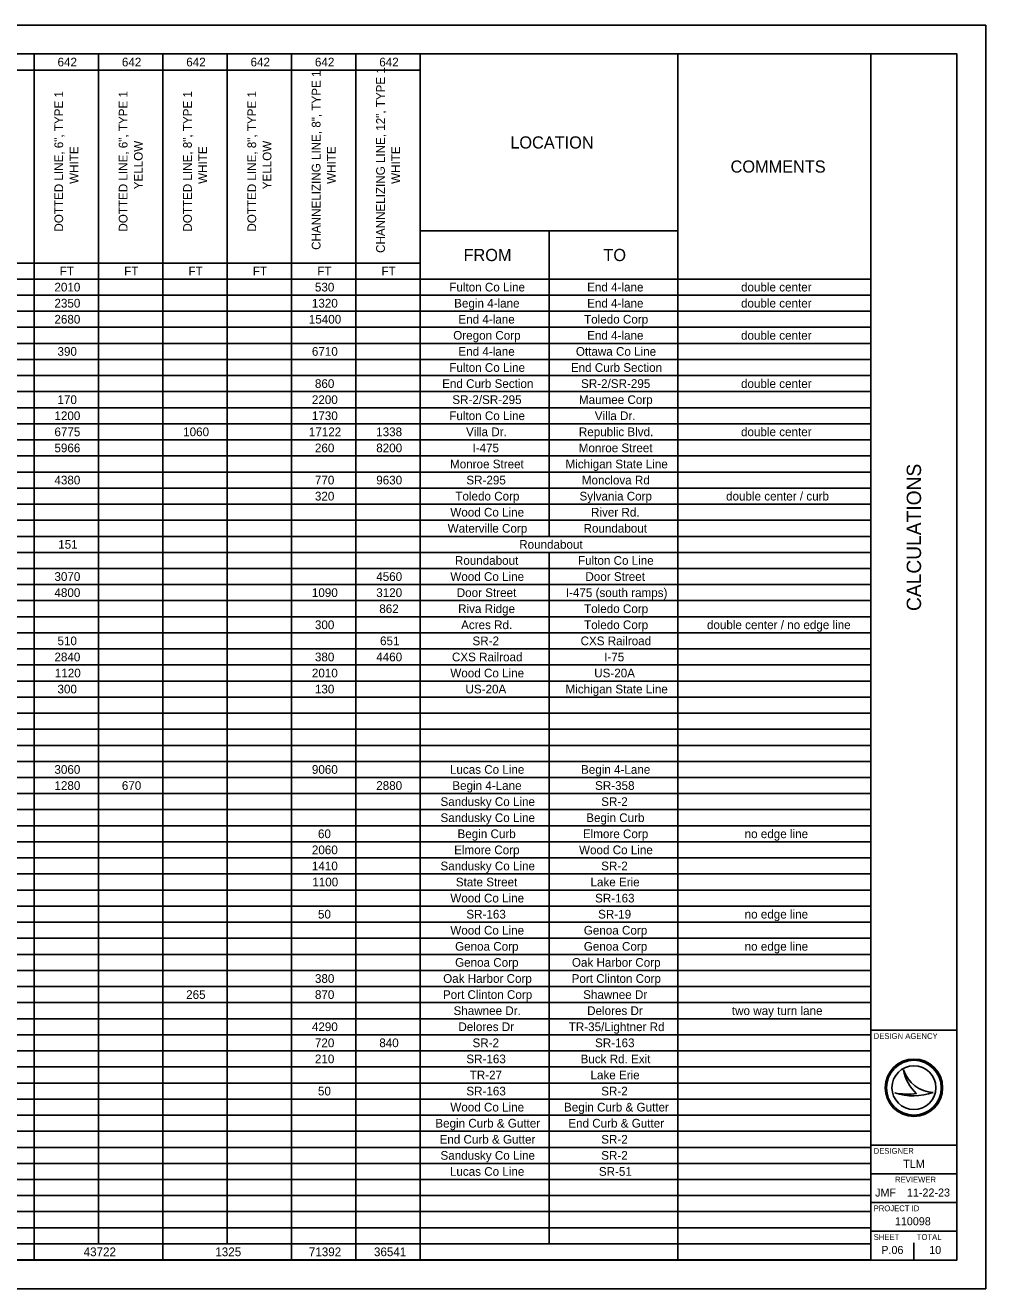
# Model space of a CAD drawing. Extents: x 0 to 34, y 0 to 22.
# Drawn here: x 17.29 to 34, y 0 to 22 of the extents above; entities that cross this region are included whole.
import ezdxf

# ---------------------------------------------------------------- set-up
doc = ezdxf.new("R2010")
doc.units = 0
for name, color, linetype in [('Default', 7, 'Continuous'), ('SH_Border', 7, 'Continuous'), ('SH_Cut_Line', 7, 'Continuous'), ('SH_Data', 7, 'Continuous')]:
    doc.layers.add(name, color=color, linetype=linetype)

msp = doc.modelspace()

# ---------------------------------------------------------------- linework, layer by layer
at = {"layer": 'Default'}
for p, q in [((1.5, 21.5), (32, 21.5)), ((17.442, 21.5), (17.442, 0.502)), ((18.562, 21.5), (18.562, 0.782)), ((19.681, 21.5), (19.681, 0.502)), ((20.801, 21.5), (20.801, 0.782)), ((21.921, 21.5), (21.921, 0.502)), ((23.041, 21.5), (23.041, 0.502)), ((24.161, 21.5), (24.161, 0.502)), ((28.64, 21.5), (28.64, 0.502)), ((32, 21.5), (32, 0.502)), ((8.483, 21.22), (24.161, 21.22)), ((24.161, 18.42), (28.64, 18.42)), ((26.401, 18.42), (26.401, 13.101)), ((8.483, 17.86), (24.161, 17.86)), ((1.5, 17.58), (32, 17.58)), ((2.505, 17.3), (32, 17.3)), ((2.505, 17.021), (32, 17.021)), ((2.505, 16.741), (32, 16.741)), ((2.505, 16.461), (32, 16.461)), ((2.505, 16.181), (32, 16.181)), ((2.505, 15.901), (32, 15.901)), ((2.505, 15.621), (32, 15.621)), ((2.505, 15.341), (32, 15.341)), ((2.505, 15.061), (32, 15.061)), ((2.505, 14.781), (32, 14.781)), ((2.505, 14.501), (32, 14.501)), ((2.505, 14.221), (32, 14.221)), ((2.505, 13.941), (32, 13.941)), ((2.505, 13.661), (32, 13.661)), ((2.505, 13.381), (32, 13.381)), ((2.505, 13.101), (32, 13.101)), ((2.505, 12.821), (32, 12.821)), ((26.401, 12.821), (26.401, 0.782)), ((2.505, 12.541), (32, 12.541)), ((2.505, 12.261), (32, 12.261)), ((2.505, 11.981), (32, 11.981)), ((2.505, 11.701), (32, 11.701)), ((2.505, 11.421), (32, 11.421)), ((2.505, 11.141), (32, 11.141)), ((2.505, 10.861), (32, 10.861)), ((2.505, 10.581), (32, 10.581)), ((1.5, 10.301), (32, 10.301)), ((1.5, 10.021), (32, 10.021)), ((1.5, 9.741), (32, 9.741)), ((1.5, 9.461), (32, 9.461)), ((1.5, 9.181), (32, 9.181)), ((2.505, 8.901), (32, 8.901)), ((2.505, 8.621), (32, 8.621)), ((2.505, 8.342), (32, 8.342)), ((2.505, 8.062), (32, 8.062)), ((2.505, 7.782), (32, 7.782)), ((2.505, 7.502), (32, 7.502)), ((2.505, 7.222), (32, 7.222)), ((2.505, 6.942), (32, 6.942)), ((2.505, 6.662), (32, 6.662)), ((2.505, 6.382), (32, 6.382)), ((2.505, 6.102), (32, 6.102)), ((2.505, 5.822), (32, 5.822)), ((2.505, 5.542), (32, 5.542)), ((2.505, 5.262), (32, 5.262)), ((2.505, 4.982), (32, 4.982)), ((2.505, 4.702), (32, 4.702)), ((2.505, 4.422), (32, 4.422)), ((2.505, 4.142), (32, 4.142)), ((2.505, 3.862), (32, 3.862)), ((2.505, 3.582), (32, 3.582)), ((2.505, 3.302), (32, 3.302)), ((2.505, 3.022), (32, 3.022)), ((2.505, 2.742), (32, 2.742)), ((2.505, 2.462), (32, 2.462)), ((2.505, 2.182), (32, 2.182)), ((1.5, 1.902), (32, 1.902)), ((1.5, 1.622), (32, 1.622)), ((1.5, 1.342), (32, 1.342)), ((1.5, 1.062), (32, 1.062)), ((1.5, 0.782), (32, 0.782)), ((1.5, 0.502), (32, 0.502))]:
    msp.add_line(p, q, dxfattribs=at)
at = {"layer": 'SH_Border'}
for p, q in [((32, 0.5), (32, 21.5)), ((32, 4.5), (33.5, 4.5)), ((32, 2.5), (33.5, 2.5)), ((32, 2), (33.5, 2)), ((32, 1.5), (33.5, 1.5)), ((32, 1), (33.5, 1))]:
    msp.add_line(p, q, dxfattribs=at)
msp.add_lwpolyline([(1.5, 21.5), (33.5, 21.5), (33.5, 0.5), (1.5, 0.5)], close=True, dxfattribs=at)
at = {"layer": 'SH_Cut_Line'}
msp.add_lwpolyline([(0, 0), (34, 0), (34, 22), (0, 22)], close=True, dxfattribs=at)
at = {"layer": 'SH_Data'}
for p, q in [((32.567, 3.81), (32.567, 3.81)), ((32.417, 3.41), (32.417, 3.41)), ((32.75, 3.5), (32.75, 3.5)), ((33.087, 3.419), (33.087, 3.419)), ((32.375, 0.675), (32.375, 0.675)), ((32.75, 0.5), (32.75, 0.8))]:
    msp.add_line(p, q, dxfattribs=at)
for radius in [0.5, 0.477, 0.477, 0.382]:
    msp.add_circle((32.75, 3.5), radius, dxfattribs=at)
for centre, radius, start, end in [((33.116, 3.998), 0.58, 198.9257, 198.9319), ((33.347, 3.97), 0.796, 191.6379, 191.6421), ((33.116, 3.998), 0.58, 198.9319, 267.1657), ((33.347, 3.97), 0.796, 191.6421, 226.0947), ((32.739, 4.37), 1.013, 251.4576, 290.0832), ((32.648, 4.654), 1.266, 259.4964, 259.4995), ((32.739, 4.37), 1.013, 251.4527, 251.4576), ((32.648, 4.654), 1.266, 259.4995, 276.6672)]:
    msp.add_arc(centre, radius, start, end, dxfattribs=at)

# ---------------------------------------------------------------- texts
at = {"layer": 'Default'}
for s, height, p in [('642', 0.1515, (17.848, 21.284)), ('642', 0.1515, (18.968, 21.284)), ('642', 0.1515, (20.088, 21.284)), ('642', 0.1515, (21.207, 21.284)), ('642', 0.1515, (22.327, 21.284)), ('642', 0.1515, (23.447, 21.284)), ('LOCATION', 0.2121, (25.727, 19.854)), ('COMMENTS', 0.2121, (29.56, 19.434)), ('FROM', 0.2121, (24.913, 17.894)), ('TO', 0.2121, (27.347, 17.894)), ('FT', 0.1515, (17.887, 17.645)), ('FT', 0.1515, (19.007, 17.645)), ('FT', 0.1515, (20.127, 17.645)), ('FT', 0.1515, (21.247, 17.645)), ('FT', 0.1515, (22.367, 17.645)), ('FT', 0.1515, (23.486, 17.645)), ('2010', 0.1515, (17.794, 17.365)), ('530', 0.1515, (22.327, 17.365)), ('Fulton Co Line', 0.15151, (24.665, 17.365)), ('End 4-lane', 0.1515, (27.064, 17.365)), ('double center', 0.15151, (29.742, 17.365)), ('2350', 0.1515, (17.794, 17.085)), ('1320', 0.1515, (22.274, 17.085)), ('Begin 4-lane', 0.15151, (24.75, 17.085)), ('End 4-lane', 0.1515, (27.064, 17.085)), ('double center', 0.15151, (29.742, 17.085)), ('2680', 0.1515, (17.794, 16.805)), ('15400', 0.1515, (22.221, 16.805)), ('End 4-lane', 0.1515, (24.824, 16.805)), ('Toledo Corp', 0.15151, (27.011, 16.805)), ('Oregon Corp', 0.15151, (24.734, 16.525)), ('End 4-lane', 0.1515, (27.064, 16.525)), ('double center', 0.15151, (29.742, 16.525)), ('390', 0.1515, (17.847, 16.245)), ('6710', 0.1515, (22.274, 16.245)), ('End 4-lane', 0.1515, (24.824, 16.245)), ('Ottawa Co Line', 0.15151, (26.868, 16.245)), ('Fulton Co Line', 0.15151, (24.665, 15.965)), ('End Curb Section', 0.15151, (26.781, 15.965)), ('End Curb Section', 0.15151, (24.541, 15.685)), ('SR-2/SR-295', 0.15151, (26.958, 15.685)), ('double center', 0.15151, (29.742, 15.685)), ('860', 0.1515, (22.327, 15.685)), ('170', 0.1515, (17.847, 15.405)), ('2200', 0.1515, (22.274, 15.405)), ('SR-2/SR-295', 0.15151, (24.718, 15.405)), ('Maumee Corp', 0.15151, (26.921, 15.405)), ('1200', 0.1515, (17.794, 15.125)), ('1730', 0.1515, (22.274, 15.125)), ('Fulton Co Line', 0.15151, (24.665, 15.125)), ('Villa Dr.', 0.1515, (27.197, 15.125)), ('6775', 0.1515, (17.794, 14.845)), ('1060', 0.1515, (20.034, 14.845)), ('17122', 0.1515, (22.221, 14.845)), ('1338', 0.1515, (23.393, 14.845)), ('Villa Dr.', 0.1515, (24.957, 14.845)), ('Republic Blvd.', 0.15151, (26.92, 14.845)), ('double center', 0.15151, (29.742, 14.845)), ('5966', 0.1515, (17.794, 14.565)), ('260', 0.1515, (22.327, 14.565)), ('8200', 0.1515, (23.394, 14.565)), ('I-475', 0.1515, (25.068, 14.565)), ('Monroe Street', 0.15151, (26.918, 14.565)), ('Monroe Street', 0.15151, (24.678, 14.285)), ('Michigan State Line', 0.15151, (26.688, 14.285)), ('4380', 0.1515, (17.794, 14.005)), ('770', 0.1515, (22.327, 14.005)), ('9630', 0.1515, (23.394, 14.005)), ('SR-295', 0.1515, (24.962, 14.005)), ('Monclova Rd', 0.15151, (26.972, 14.005)), ('320', 0.1515, (22.327, 13.725)), ('Toledo Corp', 0.15151, (24.771, 13.725)), ('Sylvania Corp', 0.15151, (26.931, 13.725)), ('double center / curb', 0.15151, (29.482, 13.725)), ('Wood Co Line', 0.15151, (24.683, 13.445)), ('River Rd.', 0.1515, (27.132, 13.445)), ('Waterville Corp', 0.15151, (24.637, 13.165)), ('Roundabout', 0.1515, (27.002, 13.165)), ('151', 0.1515, (17.86, 12.885)), ('Roundabout', 0.1515, (25.882, 12.885)), ('Roundabout', 0.1515, (24.763, 12.605)), ('Fulton Co Line', 0.15151, (26.905, 12.605)), ('3070', 0.1515, (17.794, 12.325)), ('4560', 0.1515, (23.394, 12.325)), ('Wood Co Line', 0.15151, (24.683, 12.325)), ('Door Street', 0.15151, (27.034, 12.325)), ('4800', 0.1515, (17.794, 12.045)), ('1090', 0.1515, (22.274, 12.045)), ('3120', 0.1515, (23.394, 12.045)), ('Door Street', 0.15151, (24.795, 12.045)), ('I-475 (south ramps)', 0.15151, (26.693, 12.045)), ('862', 0.1515, (23.447, 11.765)), ('Riva Ridge', 0.1515, (24.819, 11.765)), ('Toledo Corp', 0.15151, (27.011, 11.765)), ('300', 0.1515, (22.327, 11.485)), ('Acres Rd.', 0.1515, (24.871, 11.485)), ('Toledo Corp', 0.15151, (27.011, 11.485)), ('double center / no edge line', 0.15151, (29.149, 11.485)), ('510', 0.1515, (17.847, 11.205)), ('651', 0.1515, (23.46, 11.205)), ('SR-2', 0.1515, (25.069, 11.205)), ('CXS Railroad', 0.15151, (26.95, 11.205)), ('2840', 0.1515, (17.794, 10.925)), ('380', 0.1515, (22.327, 10.925)), ('4460', 0.1515, (23.394, 10.925)), ('CXS Railroad', 0.15151, (24.711, 10.925)), ('I-75', 0.1515, (27.36, 10.925)), ('1120', 0.1515, (17.801, 10.645)), ('2010', 0.1515, (22.274, 10.645)), ('Wood Co Line', 0.15151, (24.683, 10.645)), ('US-20A', 0.1515, (27.187, 10.645)), ('300', 0.1515, (17.847, 10.366)), ('130', 0.1515, (22.327, 10.366)), ('US-20A', 0.1515, (24.947, 10.366)), ('Michigan State Line', 0.15151, (26.688, 10.366)), ('3060', 0.1515, (17.794, 8.966)), ('9060', 0.1515, (22.274, 8.966)), ('Lucas Co Line', 0.15151, (24.676, 8.966)), ('Begin 4-Lane', 0.15151, (26.958, 8.966)), ('1280', 0.1515, (17.794, 8.686)), ('670', 0.1515, (18.967, 8.686)), ('2880', 0.1515, (23.394, 8.686)), ('Begin 4-Lane', 0.15151, (24.718, 8.686)), ('SR-358', 0.1515, (27.202, 8.686)), ('Sandusky Co Line', 0.15151, (24.512, 8.406)), ('SR-2', 0.1515, (27.309, 8.406)), ('Sandusky Co Line', 0.15151, (24.512, 8.126)), ('Begin Curb', 0.1515, (27.048, 8.126)), ('60', 0.1515, (22.38, 7.846)), ('Begin Curb', 0.1515, (24.808, 7.846)), ('Elmore Corp', 0.15151, (26.99, 7.846)), ('no edge line', 0.15151, (29.805, 7.846)), ('2060', 0.1515, (22.274, 7.566)), ('Elmore Corp', 0.15151, (24.75, 7.566)), ('Wood Co Line', 0.15151, (26.923, 7.566)), ('1410', 0.1515, (22.274, 7.286)), ('Sandusky Co Line', 0.15151, (24.512, 7.286)), ('SR-2', 0.1515, (27.309, 7.286)), ('1100', 0.1515, (22.281, 7.006)), ('State Street', 0.15151, (24.779, 7.006)), ('Lake Erie', 0.1515, (27.122, 7.006)), ('Wood Co Line', 0.15151, (24.683, 6.726)), ('SR-163', 0.1515, (27.202, 6.726)), ('no edge line', 0.15151, (29.805, 6.446)), ('50', 0.1515, (22.38, 6.446)), ('SR-163', 0.1515, (24.962, 6.446)), ('SR-19', 0.1515, (27.255, 6.446)), ('Wood Co Line', 0.15151, (24.683, 6.166)), ('Genoa Corp', 0.1515, (27.006, 6.166)), ('Genoa Corp', 0.1515, (24.766, 5.886)), ('Genoa Corp', 0.1515, (27.006, 5.886)), ('no edge line', 0.15151, (29.805, 5.886)), ('Genoa Corp', 0.1515, (24.766, 5.606)), ('Oak Harbor Corp', 0.15151, (26.799, 5.606)), ('380', 0.1515, (22.327, 5.326)), ('Oak Harbor Corp', 0.15151, (24.559, 5.326)), ('Port Clinton Corp', 0.15151, (26.794, 5.326)), ('265', 0.1515, (20.086, 5.046)), ('870', 0.1515, (22.327, 5.046)), ('Port Clinton Corp', 0.15151, (24.554, 5.046)), ('Shawnee Dr', 0.1515, (26.995, 5.046)), ('Shawnee Dr.', 0.15151, (24.739, 4.766)), ('Delores Dr', 0.1515, (27.064, 4.766)), ('two way turn lane', 0.15151, (29.583, 4.766)), ('4290', 0.1515, (22.274, 4.486)), ('Delores Dr', 0.1515, (24.824, 4.486)), ('TR-35/Lightner Rd', 0.15151, (26.744, 4.486)), ('720', 0.1515, (22.327, 4.206)), ('840', 0.1515, (23.447, 4.206)), ('SR-2', 0.1515, (25.069, 4.206)), ('SR-163', 0.1515, (27.202, 4.206)), ('210', 0.1515, (22.327, 3.926)), ('SR-163', 0.1515, (24.962, 3.926)), ('Buck Rd. Exit', 0.15151, (26.95, 3.926)), ('TR-27', 0.1515, (25.02, 3.646)), ('Lake Erie', 0.1515, (27.122, 3.646)), ('50', 0.1515, (22.38, 3.366)), ('SR-163', 0.1515, (24.962, 3.366)), ('SR-2', 0.1515, (27.309, 3.366)), ('Wood Co Line', 0.15151, (24.683, 3.086)), ('Begin Curb & Gutter', 0.15151, (26.662, 3.086)), ('Begin Curb & Gutter', 0.15151, (24.422, 2.806)), ('End Curb & Gutter', 0.15151, (26.736, 2.806)), ('End Curb & Gutter', 0.15151, (24.496, 2.526)), ('SR-2', 0.1515, (27.309, 2.526)), ('Sandusky Co Line', 0.15151, (24.512, 2.246)), ('SR-2', 0.1515, (27.309, 2.246)), ('Lucas Co Line', 0.15151, (24.676, 1.966)), ('SR-51', 0.1515, (27.268, 1.966)), ('43722', 0.1515, (18.302, 0.567)), ('1325', 0.1515, (20.593, 0.567)), ('71392', 0.1515, (22.221, 0.567)), ('36541', 0.1515, (23.354, 0.567))]:
    msp.add_text(s, height=height, dxfattribs=at).set_placement(p)
for s, height, p in [('CHANNELIZING LINE, 8", TYPE 1', 0.15151, (22.424, 18.089)), ('CHANNELIZING LINE, 12", TYPE 1', 0.15151, (23.544, 18.036)), ('DOTTED LINE, 6", TYPE 1', 0.15151, (17.945, 18.407)), ('DOTTED LINE, 6", TYPE 1', 0.15151, (19.065, 18.407)), ('DOTTED LINE, 8", TYPE 1', 0.15151, (20.185, 18.407)), ('DOTTED LINE, 8", TYPE 1', 0.15151, (21.304, 18.407)), ('WHITE', 0.1515, (18.21, 19.238)), ('YELLOW', 0.1515, (19.33, 19.144)), ('WHITE', 0.1515, (20.45, 19.238)), ('YELLOW', 0.1515, (21.57, 19.144)), ('WHITE', 0.1515, (22.689, 19.238)), ('WHITE', 0.1515, (23.809, 19.238))]:
    msp.add_text(s, height=height, rotation=90, dxfattribs=at).set_placement(p)
at = {"layer": 'SH_Data'}
msp.add_text('CALCULATIONS', height=0.25, rotation=90, dxfattribs=at).set_placement((32.875, 11.801))
for s, height, p in [('DESIGN AGENCY', 0.1, (32.05, 4.35)), ('DESIGNER', 0.1, (32.05, 2.35)), ('TLM', 0.14, (32.565, 2.105)), ('REVIEWER', 0.1, (32.422, 1.85)), ('JMF', 0.14, (32.075, 1.605)), ('11-22-23', 0.14, (32.629, 1.605)), ('PROJECT ID', 0.1, (32.05, 1.35)), ('110098', 0.14, (32.419, 1.105)), ('SHEET', 0.1, (32.05, 0.85)), ('TOTAL', 0.1, (32.8, 0.85)), ('P.06', 0.14, (32.183, 0.605)), ('10', 0.14, (33.017, 0.605))]:
    msp.add_text(s, height=height, dxfattribs=at).set_placement(p)

doc.saveas('drawing.dxf')
